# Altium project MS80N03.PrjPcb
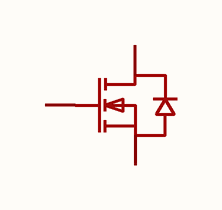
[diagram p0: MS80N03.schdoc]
1 sheet, 1 parts. Net scope: global (net labels, ports and power ports of the same name join across sheets).

## Sheet MS80N03.schdoc
size 127 x 101 mm

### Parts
Q?  ms80n03  [TO-252-2_L6.6-W6.1-P4.58-LS9.9-BR]  (value not drawn)

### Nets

Not connected (* = marked no-connect by the designer): Q? 1(G) 2(D) 3(S)

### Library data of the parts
Q? = ms80n03: 数量:1个N沟道;漏源电压(Vdss):30V;连续漏极电流(Id):80A;导通电阻(RDS(on)):3.5mΩ@10V；7mΩ@4.5V;耗散功率(Pd):105W;阈值电压(Vgs(th)):1.7V;; Manufacturer: MSKSEMI(美森科); AddInBom: yes; ModelId: ce57f84d66384067af8a68020b6de06d; ModelName: TO-252-2L-3P_L6.6-W6.1-H2.3-LS10.1-P4.6; ModelTransform: 259.842,390.52442,0,90,0,0,-39.375,0,0; Number: 1个N沟道; Drain to Source Voltage: 30V; Current - Continuous Drain(Id): 80A; Pd - Power Dissipation: 105W; Gate Threshold Voltage (Vgs(th)): 1.7V; Gate Charge(Qg): 41nC@10V; Input Capacitance(Ciss): 1.963nF; Reverse Transfer Capacitance (Crss@Vds): 221pF; Type: N沟道; Output Capacitance(Coss): 248pF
